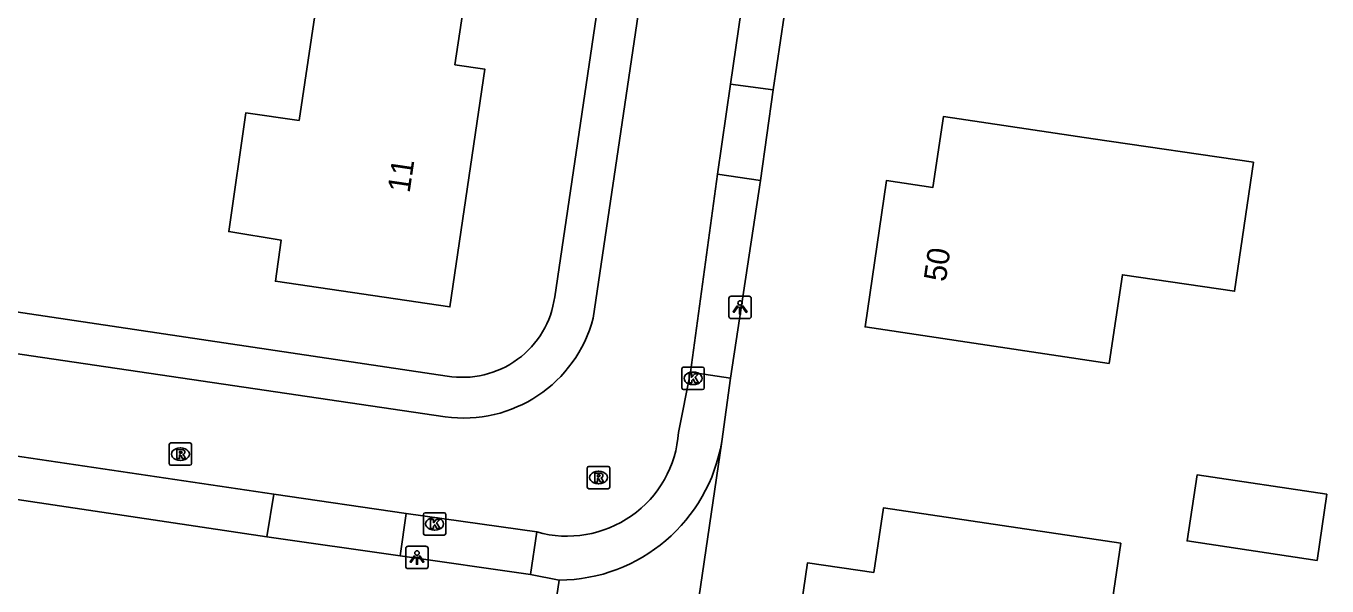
# Model space of a CAD drawing. Extents: x 164150 to 165261, y 382513 to 383432.
# Drawn here: x 164577.4 to 164635.6, y 383053.9 to 383078.9 of the extents above; entities that cross this region are included whole.
import ezdxf

# ---------------------------------------------------------------- set-up
doc = ezdxf.new("R2010")
doc.units = 0
for name, color, linetype in [('IMGEO_Kolk', 7, 'Continuous'), ('IMGEO_Lichtpunt', 7, 'Continuous'), ('IMGEO_Pand', 7, 'Continuous'), ('IMGEO_Pand_nummerreeks', 7, 'Continuous'), ('IMGEO_Parkeervlak_open', 7, 'Continuous'), ('IMGEO_Rijbaan_lokaal_open', 7, 'Continuous'), ('IMGEO_Rioolput', 7, 'Continuous'), ('IMGEO_Voetpad_gesloten', 7, 'Continuous'), ('IMGEO_Voetpad_open', 7, 'Continuous')]:
    doc.layers.add(name, color=color, linetype=linetype)

msp = doc.modelspace()

# ---------------------------------------------------------------- linework, layer by layer
at = {"layer": 'IMGEO_Kolk'}
for p, q in [((164606.767, 383062.745), (164606.767, 383063.597)), ((164606.842, 383063.671), (164607.694, 383063.671)), ((164607.255, 383063.451), (164607.28, 383063.451)), ((164607.768, 383063.597), (164607.768, 383062.745)), ((164607.694, 383062.671), (164606.842, 383062.671)), ((164607.278, 383062.891), (164607.253, 383062.891)), ((164595.211, 383056.236), (164595.211, 383057.088)), ((164595.286, 383057.162), (164596.138, 383057.162)), ((164595.699, 383056.942), (164595.724, 383056.942)), ((164596.212, 383057.088), (164596.212, 383056.236)), ((164595.722, 383056.382), (164595.697, 383056.382)), ((164596.138, 383056.162), (164595.286, 383056.162))]:
    msp.add_line(p, q, dxfattribs=at)
for points in [[(164606.767, 383062.745), (164606.767, 383063.597)], [(164606.842, 383063.671), (164607.694, 383063.671)], [(164607.088, 383063.371), (164607.211, 383063.371), (164607.211, 383063.22), (164607.341, 383063.371), (164607.505, 383063.371), (164607.359, 383063.22), (164607.512, 383062.971), (164607.36, 383062.971), (164607.275, 383063.135), (164607.211, 383063.068), (164607.211, 383062.971), (164607.088, 383062.971), (164607.088, 383063.371)], [(164607.768, 383063.597), (164607.768, 383062.745)], [(164607.694, 383062.671), (164606.842, 383062.671)], [(164595.211, 383056.236), (164595.211, 383057.088)], [(164595.286, 383057.162), (164596.138, 383057.162)], [(164595.532, 383056.862), (164595.655, 383056.862), (164595.655, 383056.711), (164595.785, 383056.862), (164595.949, 383056.862), (164595.803, 383056.711), (164595.956, 383056.462), (164595.804, 383056.462), (164595.719, 383056.626), (164595.655, 383056.559), (164595.655, 383056.462), (164595.532, 383056.462), (164595.532, 383056.862)], [(164596.212, 383057.088), (164596.212, 383056.236)], [(164596.138, 383056.162), (164595.286, 383056.162)]]:
    msp.add_lwpolyline(points, dxfattribs=at)
for centre, start, end in [((164606.844, 383063.595), 91.55205, 178.44795), ((164606.844, 383063.595), 91.55205, 178.44795), ((164607.692, 383063.595), 1.55205, 88.44795), ((164607.692, 383063.595), 1.55205, 88.44795), ((164606.844, 383062.747), 181.55205, 268.44795), ((164606.844, 383062.747), 181.55205, 268.44795), ((164607.692, 383062.747), 271.55205, 358.44795), ((164607.692, 383062.747), 271.55205, 358.44795), ((164595.288, 383057.086), 91.55205, 178.44795), ((164595.288, 383057.086), 91.55205, 178.44795), ((164596.136, 383057.086), 1.55205, 88.44795), ((164596.136, 383057.086), 1.55205, 88.44795), ((164595.288, 383056.238), 181.55205, 268.44795), ((164595.288, 383056.238), 181.55205, 268.44795), ((164596.136, 383056.238), 271.55205, 358.44795), ((164596.136, 383056.238), 271.55205, 358.44795)]:
    msp.add_arc(centre, 0.0765, start, end, dxfattribs=at)
for centre, major_axis, ratio, start_param, end_param in [((164607.254, 383063.171), (-0.387, 0.002), 0.722429, 4.712389, 7.853982), ((164607.279, 383063.171), (-0.39, 0.002), 0.717154, 1.570796, 4.712389), ((164595.698, 383056.662), (-0.387, 0.002), 0.722429, 4.712389, 7.853982), ((164595.723, 383056.662), (-0.39, 0.002), 0.717154, 1.570796, 4.712389)]:
    msp.add_ellipse(centre, major_axis=major_axis, ratio=ratio, start_param=start_param, end_param=end_param, dxfattribs=at)
at = {"layer": 'IMGEO_Lichtpunt'}
for p, q in [((164608.869, 383066.744), (164608.869, 383065.937)), ((164608.869, 383066.744), (164608.869, 383065.937)), ((164609.771, 383066.839), (164608.963, 383066.839)), ((164609.771, 383066.839), (164608.963, 383066.839)), ((164609.865, 383065.937), (164609.865, 383066.744)), ((164609.865, 383065.937), (164609.865, 383066.744)), ((164608.963, 383065.843), (164609.771, 383065.843)), ((164608.963, 383065.843), (164609.771, 383065.843)), ((164594.425, 383055.563), (164594.425, 383054.756)), ((164594.425, 383055.563), (164594.425, 383054.756)), ((164595.327, 383055.658), (164594.519, 383055.658)), ((164595.327, 383055.658), (164594.519, 383055.658)), ((164595.421, 383054.756), (164595.421, 383055.563)), ((164595.421, 383054.756), (164595.421, 383055.563)), ((164594.519, 383054.662), (164595.327, 383054.662)), ((164594.519, 383054.662), (164595.327, 383054.662))]:
    msp.add_line(p, q, dxfattribs=at)
for points in [[(164609.243, 383066.408), (164609.282, 383066.38), (164609.094, 383066.118), (164609.056, 383066.145), (164609.243, 383066.408)], [(164609.345, 383066.36), (164609.392, 383066.36), (164609.392, 383066.038), (164609.345, 383066.038), (164609.345, 383066.36)], [(164609.455, 383066.38), (164609.493, 383066.407), (164609.68, 383066.145), (164609.641, 383066.117), (164609.455, 383066.38)], [(164594.799, 383055.227), (164594.838, 383055.199), (164594.65, 383054.937), (164594.612, 383054.964), (164594.799, 383055.227)], [(164594.901, 383055.179), (164594.948, 383055.179), (164594.948, 383054.857), (164594.901, 383054.857), (164594.901, 383055.179)], [(164595.011, 383055.199), (164595.049, 383055.226), (164595.236, 383054.964), (164595.197, 383054.936), (164595.011, 383055.199)]]:
    msp.add_lwpolyline(points, dxfattribs=at)
for centre in [(164609.368, 383066.542), (164594.924, 383055.361)]:
    msp.add_circle(centre, 0.0994, dxfattribs=at)
for centre, start, end in [((164608.963, 383066.744), 90, 180), ((164608.963, 383066.744), 90, 180), ((164609.771, 383066.744), 0, 90), ((164609.771, 383066.744), 0, 90), ((164608.963, 383065.937), 180, 270), ((164608.963, 383065.937), 180, 270), ((164609.771, 383065.937), 270, 0), ((164609.771, 383065.937), 270, 360), ((164594.519, 383055.563), 90, 180), ((164594.519, 383055.563), 90, 180), ((164595.327, 383055.563), 0, 90), ((164595.327, 383055.563), 0, 90), ((164594.519, 383054.756), 180, 270), ((164594.519, 383054.756), 180, 270), ((164595.327, 383054.756), 270, 0), ((164595.327, 383054.756), 270, 360)]:
    msp.add_arc(centre, 0.0946, start, end, dxfattribs=at)
at = {"layer": 'IMGEO_Pand'}
for points in [[(164597.068, 383080.159), (164596.621, 383077.189), (164597.958, 383076.991), (164596.394, 383066.366), (164588.593, 383067.513), (164588.857, 383069.348), (164586.505, 383069.731), (164587.274, 383075.049), (164589.65, 383074.705), (164590.61, 383081.103), (164597.068, 383080.159)], [(164632.327, 383072.829), (164631.477, 383067.062), (164626.458, 383067.802), (164625.866, 383063.839), (164614.959, 383065.468), (164615.908, 383072.01), (164617.986, 383071.709), (164618.456, 383074.875), (164625.156, 383073.887), (164632.327, 383072.829)], [(164635.607, 383057.985), (164635.166, 383055.03), (164629.356, 383055.898), (164629.797, 383058.853), (164635.607, 383057.985)], [(164626.397, 383055.807), (164625.246, 383048.04), (164623.416, 383048.311), (164623.066, 383045.947), (164617.729, 383046.687), (164618.082, 383049.092), (164611.669, 383050.033), (164612.387, 383054.927), (164615.345, 383054.495), (164615.785, 383057.38), (164626.397, 383055.807)]]:
    msp.add_lwpolyline(points, dxfattribs=at)
at = {"layer": 'IMGEO_Parkeervlak_open'}
for points in [[(164612.816, 383089.325), (164610.85, 383076.068)], [(164610.275, 383072.012), (164608.947, 383063.175)], [(164588.211, 383056.086), (164572.546, 383058.416)], [(164600.005, 383054.394), (164594.166, 383055.226)]]:
    msp.add_lwpolyline(points, dxfattribs=at)
at = {"layer": 'IMGEO_Rijbaan_lokaal_open'}
for points in [[(164602.804, 383065.865), (164617.29, 383163.645)], [(164610.859, 383089.558), (164608.944, 383076.319)], [(164608.944, 383076.319), (164608.365, 383072.304)], [(164608.365, 383072.304), (164607.151, 383063.443)], [(164553.594, 383067.724), (164596.181, 383061.451)], [(164607.151, 383063.443), (164606.618, 383060.753)], [(164608.549, 383060.35), (164603.815, 383028.066)], [(164588.521, 383057.995), (164572.816, 383060.315)], [(164594.437, 383057.126), (164588.521, 383057.995)], [(164600.284, 383056.301), (164594.437, 383057.126)], [(164597.531, 383028.965), (164601.28, 383054.146)]]:
    msp.add_lwpolyline(points, dxfattribs=at)
for centre, radius, start, end in [((164597.01, 383067.383), 5.989, 262.04359, 345.32057), ((164601.638, 383061.106), 4.993, 254.26456, 355.94016), ((164601.24, 383061.553), 7.407, 270.30625, 350.65443)]:
    msp.add_arc(centre, radius, start, end, dxfattribs=at)
at = {"layer": 'IMGEO_Rioolput'}
for p, q in [((164583.847, 383059.355), (164583.847, 383060.207)), ((164583.922, 383060.281), (164584.774, 383060.281)), ((164584.335, 383060.061), (164584.36, 383060.061)), ((164584.848, 383060.207), (164584.848, 383059.355)), ((164584.774, 383059.281), (164583.922, 383059.281)), ((164584.358, 383059.501), (164584.333, 383059.501)), ((164602.614, 383059.234), (164603.466, 383059.234)), ((164602.539, 383058.308), (164602.539, 383059.16)), ((164603.027, 383059.014), (164603.052, 383059.014)), ((164603.54, 383059.16), (164603.54, 383058.308)), ((164603.466, 383058.234), (164602.614, 383058.234)), ((164603.05, 383058.454), (164603.025, 383058.454))]:
    msp.add_line(p, q, dxfattribs=at)
for points in [[(164583.847, 383059.355), (164583.847, 383060.207)], [(164583.922, 383060.281), (164584.774, 383060.281)], [(164584.436, 383059.979), (164584.184, 383059.981), (164584.184, 383059.581)], [(164584.184, 383059.581), (164584.308, 383059.581), (164584.308, 383059.743), (164584.319, 383059.743)], [(164584.362, 383059.9), (164584.308, 383059.9), (164584.308, 383059.819)], [(164584.308, 383059.819), (164584.36, 383059.819)], [(164584.848, 383060.207), (164584.848, 383059.355)], [(164584.774, 383059.281), (164583.922, 383059.281)], [(164584.366, 383059.714), (164584.437, 383059.581), (164584.577, 383059.581), (164584.512, 383059.707)], [(164602.614, 383059.234), (164603.466, 383059.234)], [(164602.539, 383058.308), (164602.539, 383059.16)], [(164603.128, 383058.932), (164602.876, 383058.934), (164602.876, 383058.534)], [(164602.876, 383058.534), (164603, 383058.534), (164603, 383058.696), (164603.011, 383058.696)], [(164603.054, 383058.853), (164603, 383058.853), (164603, 383058.772)], [(164603, 383058.772), (164603.052, 383058.772)], [(164603.058, 383058.667), (164603.129, 383058.534), (164603.269, 383058.534), (164603.204, 383058.66)], [(164603.54, 383059.16), (164603.54, 383058.308)], [(164603.466, 383058.234), (164602.614, 383058.234)]]:
    msp.add_lwpolyline(points, dxfattribs=at)
for centre, radius, start, end in [((164583.924, 383060.205), 0.0765, 91.55205, 178.44795), ((164583.924, 383060.205), 0.0765, 91.55205, 178.44795), ((164584.318, 383059.69), 0.0533, 26.02933, 88.69889), ((164584.344, 383060.008), 0.19, 274.7715, 282.96867), ((164584.368, 383059.804), 0.0964, 77.00612, 93.18647), ((164584.382, 383059.861), 0.0378, 276.66336, 79.67722), ((164584.435, 383059.869), 0.109, 350.36119, 89.41601), ((164584.433, 383059.869), 0.112, 277.58423, 350.98172), ((164584.417, 383059.654), 0.108, 29.51342, 73.79051), ((164584.772, 383060.205), 0.0765, 1.55205, 88.44795), ((164584.772, 383060.205), 0.0765, 1.55205, 88.44795), ((164583.924, 383059.357), 0.0765, 181.55205, 268.44795), ((164583.924, 383059.357), 0.0765, 181.55205, 268.44795), ((164584.772, 383059.357), 0.0765, 271.55205, 358.44795), ((164584.772, 383059.357), 0.0765, 271.55205, 358.44795), ((164602.616, 383059.158), 0.0765, 91.55205, 178.44795), ((164602.616, 383059.158), 0.0765, 91.55205, 178.44795), ((164603.464, 383059.158), 0.0765, 1.55205, 88.44795), ((164603.464, 383059.158), 0.0765, 1.55205, 88.44795), ((164603.01, 383058.643), 0.0533, 26.02933, 88.69889), ((164603.036, 383058.961), 0.19, 274.7715, 282.96867), ((164603.06, 383058.757), 0.0964, 77.00612, 93.18647), ((164603.074, 383058.814), 0.0378, 276.66336, 79.67722), ((164603.127, 383058.822), 0.109, 350.36119, 89.41601), ((164603.125, 383058.822), 0.112, 277.58423, 350.98172), ((164603.109, 383058.607), 0.108, 29.51342, 73.79051), ((164602.616, 383058.31), 0.0765, 181.55205, 268.44795), ((164602.616, 383058.31), 0.0765, 181.55205, 268.44795), ((164603.464, 383058.31), 0.0765, 271.55205, 358.44795), ((164603.464, 383058.31), 0.0765, 271.55205, 358.44795)]:
    msp.add_arc(centre, radius, start, end, dxfattribs=at)
for centre, major_axis, ratio, start_param, end_param in [((164584.334, 383059.781), (-0.387, 0.002), 0.722429, 4.712389, 7.853982), ((164584.359, 383059.781), (-0.39, 0.002), 0.717154, 1.570796, 4.712389), ((164603.026, 383058.734), (-0.387, 0.002), 0.722429, 4.712389, 7.853982), ((164603.051, 383058.734), (-0.39, 0.002), 0.717154, 1.570796, 4.712389)]:
    msp.add_ellipse(centre, major_axis=major_axis, ratio=ratio, start_param=start_param, end_param=end_param, dxfattribs=at)
at = {"layer": 'IMGEO_Voetpad_gesloten'}
for points in [[(164601.081, 383066.812), (164615.508, 383164.456)], [(164554.918, 383069.432), (164596.268, 383063.274)]]:
    msp.add_lwpolyline(points, dxfattribs=at)
msp.add_arc((164596.962, 383067.372), 4.157, 260.38548, 352.25318, dxfattribs=at)
at = {"layer": 'IMGEO_Voetpad_open'}
for points in [[(164610.85, 383076.068), (164608.944, 383076.319)], [(164610.85, 383076.068), (164610.275, 383072.012)], [(164608.365, 383072.304), (164610.275, 383072.012)], [(164608.947, 383063.175), (164607.151, 383063.443)], [(164608.947, 383063.175), (164608.549, 383060.35)], [(164588.211, 383056.086), (164588.521, 383057.995)], [(164594.437, 383057.126), (164594.166, 383055.226)], [(164600.284, 383056.301), (164600.005, 383054.394)], [(164594.166, 383055.226), (164588.211, 383056.086)], [(164601.28, 383054.146), (164600.005, 383054.394)]]:
    msp.add_lwpolyline(points, dxfattribs=at)

# ---------------------------------------------------------------- texts
at = {"layer": 'IMGEO_Pand_nummerreeks'}
for s, rotation, p in [('11', 81.62472, (164594.592, 383071.43)), ('50', 81.74535, (164618.562, 383067.456))]:
    msp.add_text(s, height=1, rotation=rotation, dxfattribs=at).set_placement(p)

doc.saveas('drawing.dxf')
